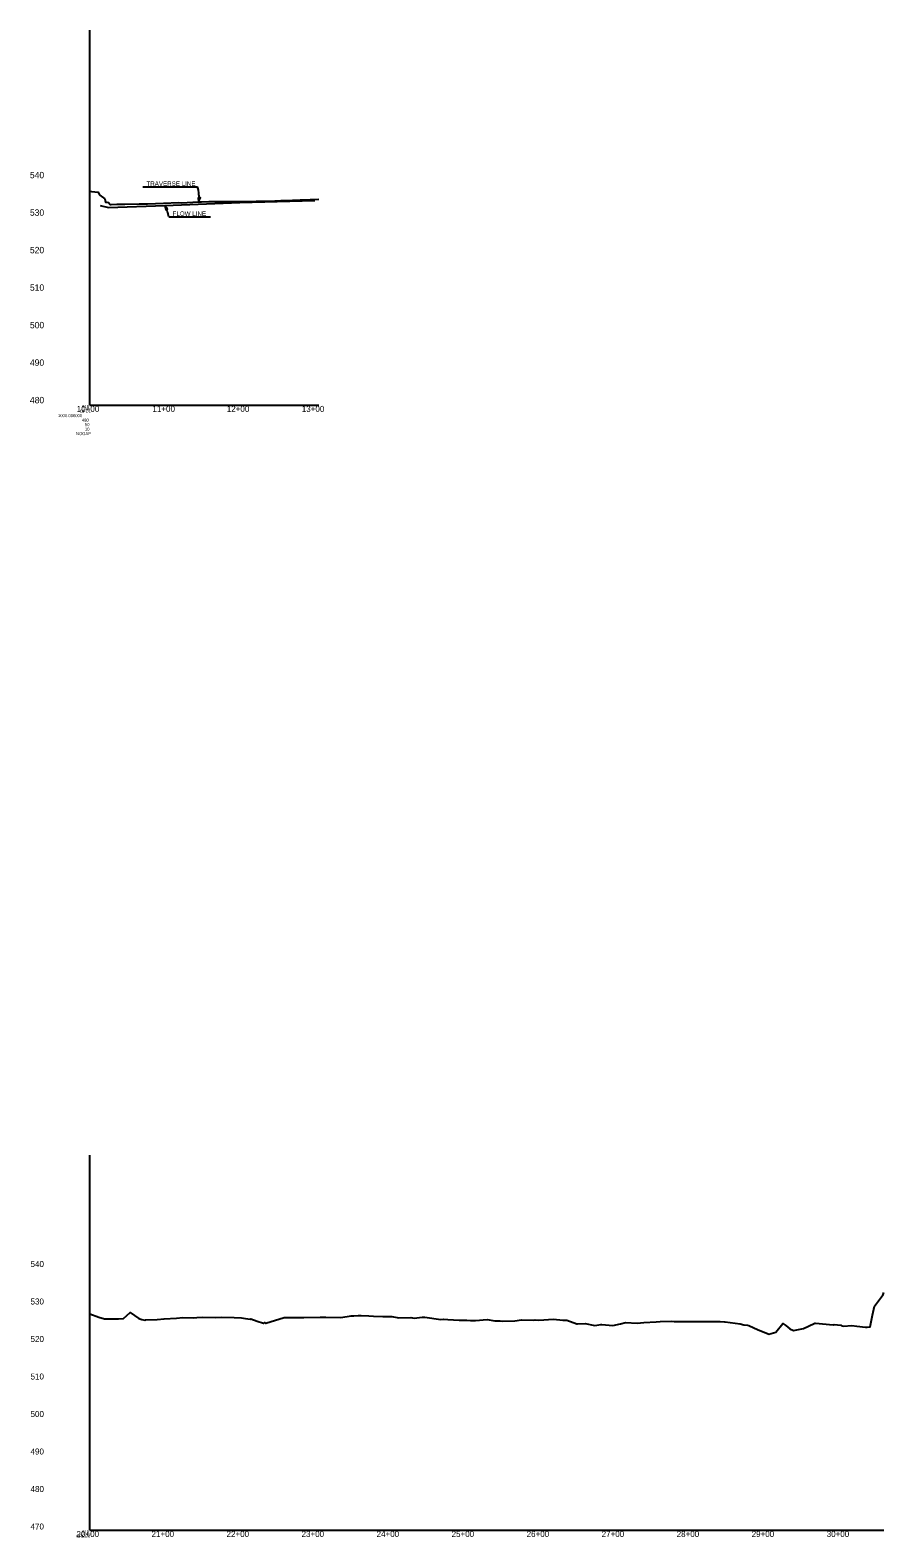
# Model space of a CAD drawing. Extents: x 1961504 to 1964196, y 1107046 to 1115093.
# Drawn here: x 1961504 to 1962642, y 1108582 to 1110593 of the extents above; entities that cross this region are included whole.
import ezdxf

# ---------------------------------------------------------------- set-up
doc = ezdxf.new("R2010")
doc.units = 0
for name, color, linetype in [('Level 40', 7, 'Continuous'), ('Level 41', 7, 'Continuous'), ('Level 42', 7, 'Continuous'), ('Level 63', 7, 'Continuous')]:
    doc.layers.add(name, color=color, linetype=linetype)

msp = doc.modelspace()

# ---------------------------------------------------------------- linework, layer by layer
at = {"layer": 'Level 40'}
for p, q in [((1961597.4, 1110358.7), (1961608.7, 1110356)), ((1961608.7, 1110356), (1961683.7, 1110358.7)), ((1961683.7, 1110358.7), (1961783.7, 1110362.8)), ((1961783.7, 1110362.8), (1961883.7, 1110365.4))]:
    msp.add_line(p, q, dxfattribs=at)
for points in [[(1961583.7, 1110377.7), (1961584.4, 1110377.8), (1961585.9, 1110377.6), (1961594.8, 1110376.6), (1961596.4, 1110373.3), (1961596.9, 1110372.5), (1961603.8, 1110367.7), (1961604.5, 1110363.2), (1961606.6, 1110363.4), (1961608.7, 1110362.7), (1961610.7, 1110360.1), (1961612.3, 1110360.3), (1961619.7, 1110360.5), (1961630.2, 1110360.7), (1961649.5, 1110361.2), (1961655.9, 1110360.9), (1961660.7, 1110361.2), (1961681.9, 1110361.8), (1961702.1, 1110362.6), (1961705.8, 1110362.5), (1961728.8, 1110363.7), (1961732.5, 1110363.7), (1961742.4, 1110363.9), (1961757.5, 1110363.9), (1961759.6, 1110364), (1961782.4, 1110364.1), (1961783.3, 1110364.1), (1961785.8, 1110364.2), (1961805.6, 1110364.6), (1961810.8, 1110364.7), (1961830.2, 1110365.2), (1961835.9, 1110365.2), (1961838.4, 1110365.3), (1961839.1, 1110365.4), (1961843.6, 1110365.6), (1961864.1, 1110366.4), (1961866.1, 1110366.5), (1961889.1, 1110367.3)], [(1962474.8, 1108860), (1962487.2, 1108855), (1962489, 1108854.2), (1962498.4, 1108856.7), (1962507.7, 1108868.4), (1962511.5, 1108865.8), (1962517, 1108861.1), (1962521.7, 1108858.9), (1962535.3, 1108861.5), (1962549.5, 1108868.2), (1962550, 1108868.7), (1962551, 1108868.8), (1962574.6, 1108866.7), (1962576.1, 1108866.9), (1962585, 1108866.1), (1962586.1, 1108865.3), (1962588.2, 1108864.7), (1962599.7, 1108865.8), (1962606.4, 1108864.6), (1962617.8, 1108863.5), (1962620.1, 1108863.3), (1962624.1, 1108863.6), (1962627, 1108879.2), (1962629.8, 1108891.2), (1962640.3, 1108905.8), (1962640.8, 1108905.5), (1962642.2, 1108909.7)], [(1961583.7, 1108881.2), (1961595.9, 1108876.9), (1961603.3, 1108874.7), (1961604.4, 1108874.6), (1961619.7, 1108874.7), (1961622.1, 1108874.4), (1961628.8, 1108874.8), (1961637.6, 1108882.9), (1961649.1, 1108875.1), (1961652.9, 1108873.7), (1961656.9, 1108872.8), (1961657.9, 1108873), (1961673.6, 1108873.5), (1961682.8, 1108874.7), (1961699.4, 1108875.2), (1961707.7, 1108876.2), (1961721.7, 1108876), (1961726.2, 1108876.2), (1961733.9, 1108876.5), (1961751.2, 1108876.2), (1961758.6, 1108876.5), (1961776.2, 1108876.2), (1961785.8, 1108875.7), (1961791.3, 1108875), (1961797.5, 1108874.2), (1961798.4, 1108874.3), (1961806.7, 1108871.3), (1961815.3, 1108868.5), (1961815.7, 1108868.9), (1961816.8, 1108869.5), (1961817.7, 1108868.9), (1961818.4, 1108868.5), (1961842.6, 1108876.1), (1961843, 1108876.1), (1961843.9, 1108876.2), (1961864.9, 1108876.2), (1961868.8, 1108876.4), (1961890.9, 1108876.5), (1961893.7, 1108876.6), (1961898.3, 1108876.9), (1961918.5, 1108876.4), (1961932.3, 1108878.5), (1961935.7, 1108878.6), (1961941.4, 1108879), (1961943.3, 1108879.1), (1961945.4, 1108879), (1961955.7, 1108878.3), (1961961.9, 1108878.2), (1961974.3, 1108877.6), (1961986.3, 1108877.7), (1961995.8, 1108875.6), (1962011.8, 1108876.4), (1962016, 1108875.5), (1962026.8, 1108876.6), (1962030.1, 1108876.9), (1962051.6, 1108873.7), (1962055.1, 1108874.2), (1962060.8, 1108873.5), (1962076, 1108872.6), (1962086.1, 1108872.9), (1962091.3, 1108872.3), (1962095.1, 1108872.1), (1962097.7, 1108872.4), (1962113.5, 1108873.5), (1962123.7, 1108871.9), (1962130.6, 1108872), (1962134.2, 1108871.4), (1962150.2, 1108871.7), (1962159.2, 1108873.1), (1962174.6, 1108872.7), (1962177.4, 1108873.1), (1962182.4, 1108872.9), (1962201.8, 1108874), (1962214.1, 1108872.7), (1962219.6, 1108872.8), (1962232.9, 1108868), (1962234, 1108867.8), (1962244.1, 1108868.4), (1962256.8, 1108865.8), (1962265, 1108867), (1962266.3, 1108866.8), (1962280.8, 1108865.5), (1962291.2, 1108868), (1962297.7, 1108869.6), (1962313.4, 1108868.7), (1962322.3, 1108869.7), (1962338.8, 1108870.3), (1962344.1, 1108870.8), (1962359, 1108871.2), (1962362.7, 1108871.1), (1962383.9, 1108871.1), (1962388.5, 1108870.9), (1962408.9, 1108870.8), (1962423.8, 1108870.8), (1962430, 1108870.6), (1962430.7, 1108870.6), (1962450.5, 1108867.9), (1962455.6, 1108866.6), (1962460.3, 1108866), (1962462.3, 1108865.5), (1962474.8, 1108860)]]:
    msp.add_lwpolyline(points, dxfattribs=at)
at = {"layer": 'Level 41'}
for p, q in [((1961727.3, 1110383.4), (1961654.2, 1110383.4)), ((1961744.6, 1110343.4), (1961689.1, 1110343.4))]:
    msp.add_line(p, q, dxfattribs=at)
for points in [[(1961687.7, 1110354.2), (1961683.7, 1110358.7), (1961684.9, 1110352.8)], [(1961728.1, 1110369.6), (1961728.8, 1110363.7), (1961731.1, 1110369.2)]]:
    msp.add_lwpolyline(points, close=True, dxfattribs=at)
for centre, radius, start, end in [((1961683.2, 1110370.1), 46.1, 351.9859, 16.8354), ((1961622.8, 1110328.4), 68.1, 12.7913, 26.4836)]:
    msp.add_arc(centre, radius, start, end, dxfattribs=at)
at = {"layer": 'Level 63'}
for p, q in [((1961583.7, 1110092.6), (1961583.7, 1110592.6)), ((1961583.7, 1110092.6), (1961889.1, 1110092.6)), ((1961583.7, 1110092.6), (1961583.7, 1110092.6)), ((1961583.7, 1108592.6), (1961583.7, 1109092.6)), ((1961583.7, 1108592.6), (1962642.2, 1108592.6)), ((1961583.7, 1108592.6), (1961583.7, 1108592.6))]:
    msp.add_line(p, q, dxfattribs=at)

# ---------------------------------------------------------------- texts
at = {"layer": 'Level 41'}
for s, p in [('TRAVERSE LINE', (1961659.2, 1110384.9)), ('FLOW LINE', (1961694.1, 1110344.9))]:
    msp.add_text(s, height=6, dxfattribs=at).set_placement(p)
at = {"layer": 'Level 42'}
for s, height, p in [('540', 8.5, (1961503.9, 1110395.1)), ('530', 8.5, (1961503.9, 1110345.1)), ('520', 8.5, (1961503.9, 1110295.1)), ('510', 8.5, (1961503.9, 1110245.1)), ('500', 8.5, (1961503.9, 1110195.1)), ('490', 8.5, (1961503.9, 1110145.1)), ('480', 8.5, (1961503.9, 1110095.1)), ('10+00', 8, (1961566.3, 1110083.6)), ('11+00', 8, (1961667.2, 1110083.6)), ('12+00', 8, (1961766.3, 1110083.6)), ('13+00', 8, (1961866.3, 1110083.6)), ('540', 8, (1961504.7, 1108943.6)), ('530', 8, (1961504.7, 1108893.6)), ('520', 8, (1961504.7, 1108843.6)), ('510', 8, (1961504.7, 1108793.6)), ('500', 8, (1961504.7, 1108743.6)), ('490', 8, (1961504.7, 1108693.6)), ('480', 8, (1961504.7, 1108643.6)), ('470', 8, (1961504.7, 1108593.6)), ('20+00', 8, (1961566, 1108583.6)), ('21+00', 8, (1961666, 1108583.6)), ('22+00', 8, (1961766, 1108583.6)), ('23+00', 8, (1961866, 1108583.6)), ('24+00', 8, (1961966, 1108583.6)), ('25+00', 8, (1962066, 1108583.6)), ('26+00', 8, (1962166, 1108583.6)), ('27+00', 8, (1962266, 1108583.6)), ('28+00', 8, (1962366, 1108583.6)), ('29+00', 8, (1962466, 1108583.6)), ('30+00', 8, (1962566, 1108583.6))]:
    msp.add_text(s, height=height, dxfattribs=at).set_placement(p)
at = {"layer": 'Level 63'}
for s, p in [('1000.000000', (1961541.3, 1110076.6)), ('OFD1', (1961570.5, 1110082.6)), ('480', (1961573.1, 1110070.6)), ('919', (1961573.4, 1110088.6)), ('NOGAP', (1961565.3, 1110052.6)), ('50', (1961577.1, 1110064.6)), ('10', (1961577.1, 1110058.6)), ('CREEK', (1961565.5, 1108582.6)), ('919', (1961573.4, 1108588.6))]:
    msp.add_text(s, height=4, dxfattribs=at).set_placement(p)

doc.saveas('drawing.dxf')
